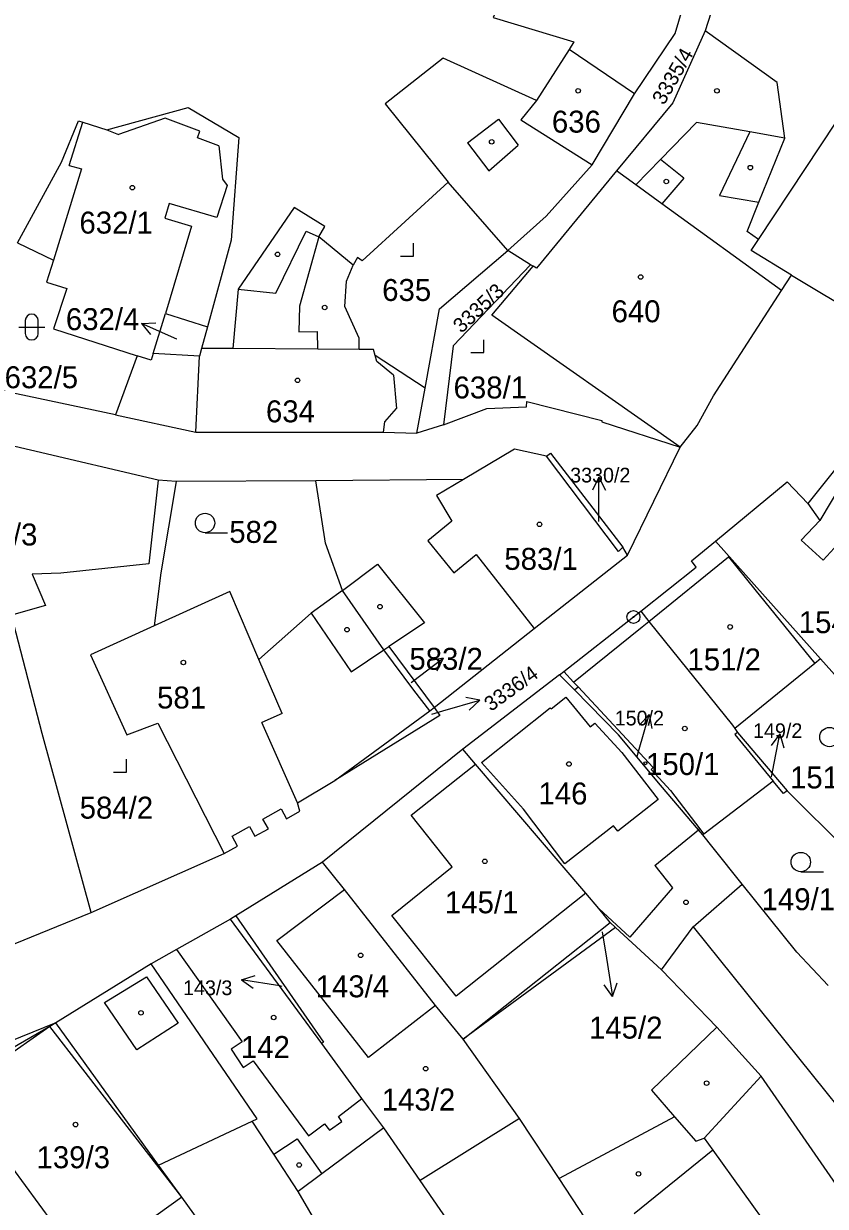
# Model space of a CAD drawing. Extents: x -600849 to -599899, y -1204328 to -1203436.
# Drawn here: x -600587.3 to -600525.3, y -1203727 to -1203635.4 of the extents above; entities that cross this region are included whole.
import ezdxf

# ---------------------------------------------------------------- set-up
doc = ezdxf.new("R2010")
doc.units = 0
for name, color, linetype in [('Vrstva 1', 7, 'Continuous'), ('Vrstva 2', 7, 'Continuous'), ('Vrstva 3', 7, 'Continuous'), ('Vrstva 4', 7, 'Continuous'), ('Vrstva 5', 7, 'Continuous'), ('Vrstva 7', 7, 'Continuous'), ('Vrstva 8', 7, 'Continuous')]:
    doc.layers.add(name, color=color, linetype=linetype)

msp = doc.modelspace()

# ---------------------------------------------------------------- linework, layer by layer
at = {"layer": 'Vrstva 1'}
for p, q in [((-600534.57, -1203635.98), (-600537.07, -1203641.56)), ((-600528.99, -1203639.99), (-600534.57, -1203635.98)), ((-600540.03, -1203640.86), (-600545.1, -1203637.43)), ((-600549.83, -1203653.01), (-600554.46, -1203647.72)), ((-600555.13, -1203657.53), (-600549.83, -1203653.01)), ((-600548.07, -1203654.1), (-600549.83, -1203653.01)), ((-600527.86, -1203654.9), (-600530.99, -1203653.01)), ((-600547.88, -1203654.22), (-600548.07, -1203654.1)), ((-600547.63, -1203654.38), (-600547.88, -1203654.22)), ((-600556.24, -1203663.66), (-600555.13, -1203657.53)), ((-600585.02, -1203659.08), (-600578.54, -1203661.16)), ((-600573.08, -1203658.92), (-600573.55, -1203660.58)), ((-600578.54, -1203661.16), (-600580.21, -1203665.74)), ((-600577.46, -1203661.5), (-600578.54, -1203661.16)), ((-600577.3, -1203660.99), (-600577.46, -1203661.5)), ((-600556.88, -1203667.16), (-600556.24, -1203663.66)), ((-600519.23, -1203663.35), (-600526.62, -1203672.61)), ((-600580.21, -1203665.74), (-600573.99, -1203667.07)), ((-600554.83, -1203666.5), (-600556.88, -1203667.16)), ((-600540.58, -1203676.59), (-600536.5, -1203668.23)), ((-600575.51, -1203670.89), (-600576.92, -1203670.78)), ((-600575.51, -1203670.89), (-600576.71, -1203677.98)), ((-600564.7, -1203670.84), (-600575.51, -1203670.89)), ((-600553.26, -1203670.74), (-600564.7, -1203670.84)), ((-600525.62, -1203684.64), (-600533.76, -1203675.51)), ((-600540.58, -1203676.59), (-600540.93, -1203675.99)), ((-600576.71, -1203677.98), (-600577.22, -1203682.07)), ((-600539.55, -1203680.94), (-600535.25, -1203677.53)), ((-600559.45, -1203683.94), (-600562.65, -1203679.34)), ((-600520.64, -1203690.25), (-600525.62, -1203684.64)), ((-600545.83, -1203685.87), (-600545.5, -1203685.62)), ((-600545.83, -1203685.87), (-600553.32, -1203691.64)), ((-600555.87, -1203688.65), (-600555.55, -1203688.4)), ((-600563.24, -1203694.06), (-600555.87, -1203688.65)), ((-600532.27, -1203690.04), (-600532.06, -1203690.34)), ((-600532.06, -1203690.34), (-600528.21, -1203694.86)), ((-600553.32, -1203691.64), (-600564.18, -1203700.38)), ((-600529.3, -1203694.1), (-600534.67, -1203698.21)), ((-600528.21, -1203694.86), (-600523.58, -1203699.44)), ((-600534.67, -1203698.21), (-600534.75, -1203698.27)), ((-600582.1, -1203704.27), (-600571.81, -1203699.72)), ((-600564.18, -1203700.38), (-600570.91, -1203704.54)), ((-600562.49, -1203702.49), (-600564.18, -1203700.38)), ((-600527.47, -1203707.35), (-600531.7, -1203702.08)), ((-600555.45, -1203711.49), (-600562.49, -1203702.49)), ((-600587.99, -1203706.68), (-600582.1, -1203704.27)), ((-600570.91, -1203704.54), (-600571.32, -1203704.79)), ((-600564.25, -1203714.43), (-600571.32, -1203704.79)), ((-600553.3, -1203714.08), (-600541.91, -1203705.05)), ((-600541.49, -1203705.45), (-600553.3, -1203714.08)), ((-600541.49, -1203705.45), (-600541.91, -1203705.05)), ((-600537.95, -1203708.73), (-600541.49, -1203705.45)), ((-600525.04, -1203709.94), (-600527.47, -1203707.35)), ((-600577.45, -1203708.25), (-600584.83, -1203712.83)), ((-600553.3, -1203714.08), (-600555.45, -1203711.49)), ((-600584.83, -1203712.83), (-600590.38, -1203715.07)), ((-600548.94, -1203720.23), (-600553.3, -1203714.08)), ((-600548.94, -1203720.23), (-600556.63, -1203725.05)), ((-600556.63, -1203725.05), (-600559.45, -1203720.96))]:
    msp.add_line(p, q, dxfattribs=at)
for points in [[(-600530.6, -1203616.71), (-600533.03, -1203631.2), (-600534.57, -1203635.98)], [(-600535.96, -1203630.46), (-600539.29, -1203627.47), (-600540.29, -1203625.92), (-600544.43, -1203625.57), (-600549.38, -1203631.43), (-600550.98, -1203634.95), (-600544.72, -1203636.85), (-600545.1, -1203637.43)], [(-600540.03, -1203640.86), (-600536.89, -1203636.19), (-600535.34, -1203630.96), (-600535.96, -1203630.46)], [(-600527.86, -1203654.9), (-600522.41, -1203658.19), (-600511.68, -1203642.2), (-600509.04, -1203638.54), (-600506.63, -1203634.51)], [(-600545.1, -1203637.43), (-600547.62, -1203641.37), (-600554.84, -1203638.11), (-600559.33, -1203641.63), (-600554.46, -1203647.72)], [(-600531.3, -1203651.53), (-600530.39, -1203649.26), (-600528.4, -1203644.29), (-600528.99, -1203639.99)], [(-600549.83, -1203653.01), (-600546.88, -1203650.35), (-600543.31, -1203646.36), (-600540.03, -1203640.86)], [(-600537.07, -1203641.56), (-600541.42, -1203646.84), (-600547.63, -1203654.38)], [(-600587.79, -1203652.4), (-600584.39, -1203646.17), (-600583.07, -1203642.96), (-600582.75, -1203643.06), (-600580.88, -1203643.65), (-600574.6, -1203641.92), (-600570.67, -1203644.25), (-600571.26, -1203652.21), (-600573.08, -1203658.92)], [(-600554.46, -1203647.72), (-600561.11, -1203653.8), (-600561.47, -1203653.55), (-600561.82, -1203654.13)], [(-600561.82, -1203654.13), (-600564.47, -1203651.94), (-600564, -1203651.13), (-600566.37, -1203649.67), (-600570.71, -1203655.99), (-600571.14, -1203660.6), (-600573.55, -1203660.58)], [(-600530.99, -1203653.01), (-600530.42, -1203652.15), (-600531.3, -1203651.53)], [(-600587.79, -1203652.4), (-600585.02, -1203653.74), (-600585.55, -1203655.46), (-600583.97, -1203655.95), (-600585.02, -1203659.08)], [(-600561.35, -1203659.79), (-600562.47, -1203657.33), (-600562.33, -1203655.37), (-600561.82, -1203654.13)], [(-600548.07, -1203654.1), (-600554.07, -1203660.38), (-600554.83, -1203666.5)], [(-600536.5, -1203668.23), (-600551.07, -1203658.01), (-600547.88, -1203654.22)], [(-600536.5, -1203668.23), (-600535.17, -1203666.55), (-600533.9, -1203664.27), (-600528.64, -1203656.09), (-600527.86, -1203654.9)], [(-600577.3, -1203660.99), (-600576.34, -1203657.88), (-600573.08, -1203658.92)], [(-600556.24, -1203663.66), (-600560.11, -1203661.14), (-600560.24, -1203660.67), (-600561.34, -1203660.66), (-600561.35, -1203659.79)], [(-600573.55, -1203660.58), (-600573.72, -1203661.19), (-600577.3, -1203660.99)], [(-600580.21, -1203665.74), (-600588.72, -1203663.92), (-600591.33, -1203663.22)], [(-600554.83, -1203666.5), (-600551.47, -1203665.24), (-600548.38, -1203665.12), (-600548.37, -1203664.7), (-600542.56, -1203666.16), (-600542.56, -1203666.26), (-600536.5, -1203668.23)], [(-600576.92, -1203670.78), (-600596.7, -1203666.14), (-600597.31, -1203668.74)], [(-600573.99, -1203667.07), (-600559.46, -1203667.07), (-600556.88, -1203667.16)], [(-600546.83, -1203668.93), (-600549.33, -1203668.39), (-600553.26, -1203670.74)], [(-600546.83, -1203668.93), (-600546.54, -1203668.71), (-600540.93, -1203675.99)], [(-600540.93, -1203675.99), (-600541.27, -1203676.31), (-600546.83, -1203668.93)], [(-600576.92, -1203670.78), (-600577.64, -1203677.26), (-600584.45, -1203678), (-600586.66, -1203678.08), (-600585.63, -1203680.51), (-600588.26, -1203681.25)], [(-600562.65, -1203679.34), (-600563.96, -1203675.66), (-600564.7, -1203670.84)], [(-600533.76, -1203675.51), (-600528.21, -1203670.91), (-600526.62, -1203672.61)], [(-600526.62, -1203672.61), (-600525.67, -1203673.91), (-600527.13, -1203675.45), (-600525.43, -1203677), (-600523.99, -1203675.43), (-600514.34, -1203683.98)], [(-600535.25, -1203677.53), (-600535.62, -1203677.04), (-600533.76, -1203675.51)], [(-600555.55, -1203688.4), (-600547.81, -1203682.29), (-600540.58, -1203676.59)], [(-600562.65, -1203679.34), (-600565.06, -1203681.09), (-600569.12, -1203684.67), (-600571.37, -1203679.42), (-600577.22, -1203682.07)], [(-600545.5, -1203685.62), (-600540.11, -1203681.39), (-600539.55, -1203680.94)], [(-600539.55, -1203680.94), (-600538.92, -1203681.73), (-600532.44, -1203689.78), (-600532.27, -1203690.04)], [(-600582.1, -1203704.27), (-600585.89, -1203690.42), (-600588.26, -1203681.25)], [(-600577.22, -1203682.07), (-600582.15, -1203684.33), (-600579.34, -1203690.53), (-600576.94, -1203689.62), (-600571.81, -1203699.72)], [(-600559.45, -1203683.94), (-600559.06, -1203683.67), (-600555.55, -1203688.4)], [(-600555.87, -1203688.65), (-600557.11, -1203687.07), (-600559.45, -1203683.94)], [(-600525.62, -1203684.64), (-600526.06, -1203685), (-600532.27, -1203690.04)], [(-600545.5, -1203685.62), (-600544.74, -1203686.44), (-600544.4, -1203686.81), (-600538.59, -1203693.05), (-600538.75, -1203693.21), (-600537.24, -1203694.82), (-600534.98, -1203697.8), (-600534.67, -1203698.21)], [(-600534.75, -1203698.27), (-600535.08, -1203697.88), (-600538.01, -1203694.41), (-600541.26, -1203690.53), (-600544.68, -1203687.04), (-600545.83, -1203685.87)], [(-600555.55, -1203688.4), (-600555.09, -1203689.01), (-600563.24, -1203694.06)], [(-600532.06, -1203690.34), (-600532.25, -1203690.49), (-600529.3, -1203694.1)], [(-600541.91, -1203705.05), (-600542.8, -1203703.96), (-600543.8, -1203702.79), (-600545.63, -1203700.65), (-600552.33, -1203692.8), (-600553.32, -1203691.64)], [(-600571.81, -1203699.72), (-600570.76, -1203699.14), (-600571.19, -1203698.38), (-600569.84, -1203697.63), (-600569.42, -1203698.38), (-600568.38, -1203697.81), (-600568.81, -1203697.05), (-600567.4, -1203696.26), (-600566.98, -1203697.02), (-600565.94, -1203696.44), (-600566.12, -1203695.78), (-600563.24, -1203694.06)], [(-600528.21, -1203694.86), (-600528.48, -1203695.07), (-600529.3, -1203694.1)], [(-600531.7, -1203702.08), (-600533.95, -1203699.28), (-600534.75, -1203698.27)], [(-600537.95, -1203708.73), (-600535.49, -1203705.4), (-600531.7, -1203702.08)], [(-600555.45, -1203711.49), (-600560.63, -1203715.51), (-600567.73, -1203706.44), (-600562.49, -1203702.49)], [(-600571.32, -1203704.79), (-600575.5, -1203707.15), (-600577.45, -1203708.25)], [(-600570.91, -1203704.54), (-600564.1, -1203714.33), (-600564.25, -1203714.43)], [(-600566.07, -1203725.89), (-600567.96, -1203723.01), (-600569.64, -1203720.45), (-600569.24, -1203720.26), (-600577.45, -1203708.25)], [(-600514.56, -1203740.22), (-600518.55, -1203733.82), (-600530.21, -1203716.96), (-600533.65, -1203713.17), (-600537.95, -1203708.73)], [(-600584.83, -1203712.83), (-600585.31, -1203713.11), (-600593, -1203717.54)], [(-600568.53, -1203735.4), (-600569.85, -1203733.61), (-600575.09, -1203726.34), (-600576.89, -1203723.85), (-600584.83, -1203712.83)], [(-600559.45, -1203720.96), (-600561.13, -1203718.68), (-600564.25, -1203714.43)], [(-600593, -1203717.54), (-600592.53, -1203718.19), (-600585.08, -1203728.33), (-600582.6, -1203731.71), (-600575.69, -1203741.13)], [(-600527.78, -1203749.32), (-600539.81, -1203733.24), (-600540.75, -1203731.96), (-600543.64, -1203728.03), (-600543.86, -1203727.95), (-600545.87, -1203724.89), (-600548.94, -1203720.23)], [(-600559.45, -1203720.96), (-600564.23, -1203724.52), (-600566.07, -1203725.89)], [(-600539.73, -1203748.47), (-600548.6, -1203736.31), (-600552.45, -1203731.03), (-600553.3, -1203729.87), (-600556.63, -1203725.05)], [(-600543.06, -1203759.7), (-600550.62, -1203748.91), (-600553.02, -1203745.37), (-600556.53, -1203739.96), (-600563.93, -1203728.43), (-600564.41, -1203728.72), (-600566.07, -1203725.89)]]:
    msp.add_lwpolyline(points, dxfattribs=at)
at = {"layer": 'Vrstva 3'}
for p, q in [((-600557.14, -1203653.44), (-600557.14, -1203652.44)), ((-600558.141, -1203653.44), (-600557.14, -1203653.44)), ((-600587.701, -1203658.931), (-600585.699, -1203658.931)), ((-600587.201, -1203658.431), (-600587.201, -1203659.432)), ((-600586.199, -1203659.432), (-600586.199, -1203658.431)), ((-600551.7, -1203660.91), (-600551.7, -1203659.91)), ((-600552.701, -1203660.91), (-600551.7, -1203660.91)), ((-600573.283, -1203674.86), (-600571.533, -1203674.86)), ((-600579.36, -1203693.4), (-600579.36, -1203692.4)), ((-600580.361, -1203693.4), (-600579.36, -1203693.4)), ((-600527.153, -1203701.12), (-600525.403, -1203701.12))]:
    msp.add_line(p, q, dxfattribs=at)
for centre in [(-600573.283, -1203674.11), (-600524.933, -1203690.69), (-600527.153, -1203700.37)]:
    msp.add_circle(centre, 0.75, dxfattribs=at)
for centre, start, end in [((-600586.7, -1203658.431), 0, 180), ((-600586.7, -1203659.431), 180, 359.98789)]:
    msp.add_arc(centre, 0.5, start, end, dxfattribs=at)
at = {"layer": 'Vrstva 4'}
for p, q in [((-600530.42, -1203652.15), (-600520.19, -1203636.64)), ((-600547.62, -1203641.37), (-600548.83, -1203642.87)), ((-600583.79, -1203646.41), (-600582.75, -1203643.06)), ((-600576.36, -1203642.76), (-600579.98, -1203644.01)), ((-600573.69, -1203643.77), (-600576.36, -1203642.76)), ((-600552.96, -1203644.66), (-600550.55, -1203642.84)), ((-600550.55, -1203642.84), (-600549.03, -1203644.84)), ((-600548.83, -1203642.87), (-600543.31, -1203646.36)), ((-600535.24, -1203643.08), (-600538.01, -1203645.94)), ((-600531.09, -1203643.81), (-600535.24, -1203643.08)), ((-600580.88, -1203643.65), (-600579.98, -1203644.01)), ((-600573.87, -1203644.27), (-600573.69, -1203643.77)), ((-600572.21, -1203644.89), (-600573.87, -1203644.27)), ((-600531.09, -1203643.81), (-600533.45, -1203648.74)), ((-600528.4, -1203644.29), (-600531.09, -1203643.81)), ((-600572.21, -1203644.89), (-600571.94, -1203647.48)), ((-600552.96, -1203644.66), (-600551.31, -1203646.84)), ((-600551.31, -1203646.84), (-600549.03, -1203644.84)), ((-600538.01, -1203645.94), (-600539.93, -1203647.92)), ((-600536.2, -1203647.39), (-600538.01, -1203645.94)), ((-600582.84, -1203646.68), (-600585.02, -1203653.74)), ((-600583.79, -1203646.41), (-600582.84, -1203646.68)), ((-600539.93, -1203647.92), (-600541.42, -1203646.84)), ((-600571.57, -1203647.96), (-600572.36, -1203650.44)), ((-600571.94, -1203647.48), (-600571.57, -1203647.96)), ((-600537.9, -1203649.39), (-600539.93, -1203647.92)), ((-600536.2, -1203647.39), (-600537.9, -1203649.39)), ((-600533.45, -1203648.74), (-600530.39, -1203649.26)), ((-600576.06, -1203649.36), (-600576.4, -1203650.5)), ((-600572.36, -1203650.44), (-600576.06, -1203649.36)), ((-600528.64, -1203656.09), (-600537.9, -1203649.39)), ((-600576.4, -1203650.5), (-600574.33, -1203651.11)), ((-600574.33, -1203651.11), (-600576.34, -1203657.88)), ((-600567.8, -1203656.3), (-600565.44, -1203651.5)), ((-600565.44, -1203651.5), (-600564.47, -1203651.94)), ((-600564.47, -1203651.94), (-600565.96, -1203657.31)), ((-600570.71, -1203655.99), (-600567.8, -1203656.3)), ((-600565.96, -1203657.31), (-600566.03, -1203659.29)), ((-600566.03, -1203659.29), (-600564.58, -1203659.27)), ((-600564.56, -1203660.64), (-600564.58, -1203659.27)), ((-600564.56, -1203660.64), (-600571.14, -1203660.6)), ((-600561.34, -1203660.66), (-600564.56, -1203660.64)), ((-600573.99, -1203667.07), (-600573.72, -1203661.19)), ((-600559.97, -1203661.61), (-600560.11, -1203661.14)), ((-600558.7, -1203662.67), (-600559.97, -1203661.61)), ((-600558.7, -1203662.67), (-600558.46, -1203665.25)), ((-600559.37, -1203666.28), (-600558.46, -1203665.25)), ((-600559.46, -1203667.07), (-600559.37, -1203666.28)), ((-600522.17, -1203667.99), (-600525.67, -1203673.91)), ((-600553.26, -1203670.74), (-600555.35, -1203671.99)), ((-600555.35, -1203671.99), (-600554.18, -1203673.98)), ((-600554.18, -1203673.98), (-600556.04, -1203675.48)), ((-600556.04, -1203675.48), (-600554.03, -1203677.97)), ((-600562.65, -1203679.34), (-600559.94, -1203677.3)), ((-600559.94, -1203677.3), (-600556.29, -1203681.85)), ((-600554.03, -1203677.97), (-600552.29, -1203676.54)), ((-600552.29, -1203676.54), (-600547.81, -1203682.29)), ((-600538.92, -1203681.73), (-600532.74, -1203676.74)), ((-600532.74, -1203676.74), (-600530.7, -1203679.27)), ((-600530.7, -1203679.27), (-600526.06, -1203685)), ((-600565.06, -1203681.09), (-600561.97, -1203685.65)), ((-600556.29, -1203681.85), (-600559.06, -1203683.67)), ((-600539.43, -1203682.14), (-600538.92, -1203681.73)), ((-600544.74, -1203686.44), (-600539.43, -1203682.14)), ((-600567.31, -1203688.86), (-600569.12, -1203684.67)), ((-600561.97, -1203685.65), (-600559.45, -1203683.94)), ((-600544.68, -1203687.04), (-600544.4, -1203686.81)), ((-600546.48, -1203688.5), (-600545.34, -1203687.59)), ((-600545.34, -1203687.59), (-600543.47, -1203689.9)), ((-600567.31, -1203688.86), (-600568.88, -1203689.56)), ((-600551.88, -1203692.67), (-600546.55, -1203688.43)), ((-600546.55, -1203688.43), (-600546.48, -1203688.5)), ((-600566.12, -1203695.78), (-600568.88, -1203689.56)), ((-600543.47, -1203689.9), (-600543.11, -1203689.61)), ((-600543.11, -1203689.61), (-600541.02, -1203691.89)), ((-600541.02, -1203691.89), (-600538.2, -1203695.52)), ((-600548.62, -1203696.27), (-600551.88, -1203692.67)), ((-600538.2, -1203695.52), (-600541.33, -1203697.98)), ((-600545.42, -1203700.5), (-600548.62, -1203696.27)), ((-600541.66, -1203697.56), (-600545.42, -1203700.5)), ((-600541.33, -1203697.98), (-600541.66, -1203697.56)), ((-600538.46, -1203700.64), (-600535.08, -1203697.88)), ((-600534.98, -1203697.8), (-600535.08, -1203697.88)), ((-600538.46, -1203700.64), (-600537.08, -1203702.37)), ((-600537.08, -1203702.37), (-600540.38, -1203706.2)), ((-600540.38, -1203706.2), (-600542.8, -1203703.96)), ((-600535.49, -1203705.4), (-600519.71, -1203725.04)), ((-600575.5, -1203707.15), (-600570.41, -1203714.31)), ((-600581.06, -1203711.24), (-600577.82, -1203709.26)), ((-600577.82, -1203709.26), (-600575.37, -1203712.84)), ((-600578.56, -1203714.91), (-600581.06, -1203711.24)), ((-600585.31, -1203713.11), (-600592.53, -1203718.19)), ((-600575.09, -1203726.34), (-600585.31, -1203713.11)), ((-600575.37, -1203712.84), (-600578.56, -1203714.91)), ((-600533.65, -1203713.17), (-600538.72, -1203718.04)), ((-600570.41, -1203714.31), (-600571.25, -1203714.86)), ((-600571.25, -1203714.86), (-600570.32, -1203716.28)), ((-600570.32, -1203716.28), (-600569.55, -1203715.78)), ((-600569.55, -1203715.78), (-600565.28, -1203721.58)), ((-600534.63, -1203721.75), (-600530.21, -1203716.96)), ((-600538.72, -1203718.04), (-600536.94, -1203720.1)), ((-600562.95, -1203720.07), (-600561.13, -1203718.68)), ((-600576.89, -1203723.85), (-600569.64, -1203720.45)), ((-600563.65, -1203721.15), (-600562.68, -1203720.48)), ((-600562.68, -1203720.48), (-600562.95, -1203720.07)), ((-600536.94, -1203720.1), (-600545.87, -1203724.89)), ((-600536.94, -1203720.1), (-600535.29, -1203721.99)), ((-600565.28, -1203721.58), (-600564.02, -1203720.64)), ((-600564.02, -1203720.64), (-600563.65, -1203721.15)), ((-600567.96, -1203723.01), (-600566.14, -1203721.8)), ((-600566.14, -1203721.8), (-600564.23, -1203724.52)), ((-600535.29, -1203721.99), (-600534.63, -1203721.75)), ((-600534.63, -1203721.75), (-600533.96, -1203722.68)), ((-600533.96, -1203722.68), (-600540.06, -1203727.63)), ((-600533.96, -1203722.68), (-600527.15, -1203732.19)), ((-600575.09, -1203726.34), (-600582.6, -1203731.71))]:
    msp.add_line(p, q, dxfattribs=at)
msp.add_lwpolyline([(-600543.8, -1203702.79), (-600553.85, -1203710.77), (-600558.82, -1203704.51), (-600554.14, -1203700.75), (-600557.32, -1203696.74), (-600552.33, -1203692.8)], dxfattribs=at)
at = {"layer": 'Vrstva 5'}
for centre, radius in [((-600544.397, -1203640.629), 0.175), ((-600533.647, -1203640.629), 0.175), ((-600551.087, -1203644.579), 0.175), ((-600531.057, -1203646.579), 0.175), ((-600578.907, -1203648.129), 0.175), ((-600537.567, -1203647.659), 0.175), ((-600567.667, -1203653.299), 0.175), ((-600539.547, -1203655.049), 0.175), ((-600564.017, -1203657.419), 0.175), ((-600566.117, -1203663.059), 0.175), ((-600547.387, -1203674.209), 0.175), ((-600559.737, -1203680.589), 0.175), ((-600532.627, -1203682.159), 0.175), ((-600562.287, -1203682.369), 0.175), ((-600574.957, -1203684.909), 0.175), ((-600536.137, -1203690.029), 0.175), ((-600545.107, -1203692.779), 0.175), ((-600539.185, -1203692.719), 0.117), ((-600551.617, -1203700.319), 0.175), ((-600536.037, -1203703.489), 0.175), ((-600561.237, -1203707.599), 0.175), ((-600578.237, -1203712.049), 0.175), ((-600567.967, -1203712.409), 0.175), ((-600556.197, -1203716.379), 0.175), ((-600534.447, -1203717.499), 0.175), ((-600583.307, -1203720.709), 0.175), ((-600565.997, -1203723.839), 0.175), ((-600539.717, -1203724.529), 0.175)]:
    msp.add_circle(centre, radius, dxfattribs=at)
at = {"layer": 'Vrstva 7'}
for p, q in [((-600578.212, -1203658.649), (-600577.093, -1203658.599)), ((-600575.47, -1203659.87), (-600578.212, -1203658.649)), ((-600578.212, -1203658.649), (-600577.5, -1203659.514)), ((-600575.46, -1203659.88), (-600575.47, -1203659.87)), ((-600542.78, -1203670.559), (-600543.281, -1203671.56)), ((-600542.78, -1203673.56), (-600542.78, -1203670.559)), ((-600542.78, -1203670.559), (-600542.279, -1203671.56)), ((-600542.78, -1203673.99), (-600542.78, -1203673.56)), ((-600557.23, -1203686.39), (-600554.833, -1203684.584)), ((-600554.833, -1203684.584), (-600555.934, -1203684.787)), ((-600554.833, -1203684.584), (-600555.332, -1203685.587)), ((-600557.33, -1203686.47), (-600557.23, -1203686.39)), ((-600554.88, -1203688.67), (-600551.995, -1203687.843)), ((-600551.995, -1203687.843), (-600553.096, -1203687.638)), ((-600551.995, -1203687.843), (-600552.82, -1203688.6)), ((-600555.71, -1203688.91), (-600554.88, -1203688.67)), ((-600539.71, -1203691.82), (-600538.883, -1203688.935)), ((-600538.883, -1203688.935), (-600539.64, -1203689.76)), ((-600538.883, -1203688.935), (-600538.678, -1203690.036)), ((-600528.767, -1203690.444), (-600529.45, -1203691.332)), ((-600529.34, -1203693.39), (-600528.767, -1203690.444)), ((-600528.767, -1203690.444), (-600528.467, -1203691.523)), ((-600539.82, -1203692.19), (-600539.71, -1203691.82)), ((-600529.41, -1203693.77), (-600529.34, -1203693.39)), ((-600542.53, -1203705.78), (-600542.19, -1203707.83)), ((-600542.19, -1203707.83), (-600541.721, -1203710.794)), ((-600570.464, -1203709.501), (-600569.397, -1203709.163)), ((-600567.5, -1203709.97), (-600570.464, -1203709.501)), ((-600570.464, -1203709.501), (-600569.553, -1203710.152)), ((-600567.31, -1203710), (-600567.5, -1203709.97)), ((-600541.721, -1203710.794), (-600542.372, -1203709.883)), ((-600541.721, -1203710.794), (-600541.383, -1203709.727))]:
    msp.add_line(p, q, dxfattribs=at)
at = {"layer": 'Vrstva 8'}
for radius in [0.5, 0.0303]:
    msp.add_circle((-600540.11, -1203681.39), radius, dxfattribs=at)

# ---------------------------------------------------------------- texts
at = {"layer": 'Vrstva 2'}
for s, rotation, p in [('3335/4', 60, (-600537.749, -1203641.797)), ('3335/3', 43, (-600553.427, -1203659.462)), ('3336/4', 36, (-600551.144, -1203688.751))]:
    msp.add_text(s, height=1.14, rotation=rotation, dxfattribs=at).set_placement(p)
for s, height, p in [('636', 1.7, (-600546.425, -1203643.87)), ('632/1', 1.7, (-600583.008, -1203651.69)), ('635', 1.7, (-600559.565, -1203656.91)), ('640', 1.7, (-600541.805, -1203658.56)), ('632/4', 1.7, (-600584.058, -1203659.17)), ('632/5', 1.7, (-600588.798, -1203663.67)), ('638/1', 1.7, (-600554.038, -1203664.46)), ('634', 1.7, (-600568.565, -1203666.31)), ('3330/2', 1.14, (-600545.01, -1203670.97)), ('584/3', 1.7, (-600591.948, -1203675.85)), ('582', 1.7, (-600571.405, -1203675.65)), ('583/1', 1.7, (-600550.108, -1203677.74)), ('154/2', 1.7, (-600527.308, -1203682.64)), ('583/2', 1.7, (-600557.458, -1203685.48)), ('151/2', 1.7, (-600535.928, -1203685.53)), ('581', 1.7, (-600576.995, -1203688.48)), ('150/2', 1.14, (-600541.56, -1203689.79)), ('149/2', 1.14, (-600530.85, -1203690.77)), ('150/1', 1.7, (-600539.138, -1203693.63)), ('151/1', 1.7, (-600527.988, -1203694.67)), ('146', 1.7, (-600547.465, -1203695.91)), ('584/2', 1.7, (-600582.988, -1203697.01)), ('145/1', 1.7, (-600554.708, -1203704.34)), ('149/1', 1.7, (-600530.188, -1203704.1)), ('143/3', 1.14, (-600574.983, -1203710.68)), ('143/4', 1.7, (-600564.718, -1203710.85)), ('145/2', 1.7, (-600543.55, -1203714.048)), ('142', 1.7, (-600570.505, -1203715.55)), ('143/2', 1.7, (-600559.598, -1203719.62)), ('139/3', 1.7, (-600586.328, -1203724.09))]:
    msp.add_text(s, height=height, dxfattribs=at).set_placement(p)

doc.saveas('drawing.dxf')
